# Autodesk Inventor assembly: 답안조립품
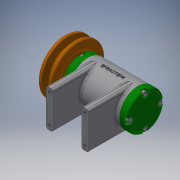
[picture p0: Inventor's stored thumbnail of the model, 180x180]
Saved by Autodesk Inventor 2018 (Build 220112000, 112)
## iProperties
Created: 2020-07
Part Number: 답안조립품
Document SubType Name: Assembly
Designer: Administrator
Author: Administrator
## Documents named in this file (15)
- C:\Users\Administrator\Desktop\700706V1038\답안조립품.iam
- C:\Users\Administrator\Desktop\700706V1038\본체 ipt.ipt
- C:\Users\Administrator\Desktop\700706V1038\V벨트풀리.ipt
- C:\Users\Administrator\Desktop\700706V1038\너트 M8.ipt
- C:\Users\Administrator\Desktop\700706V1038\뒤커버.ipt
- C:\Users\Administrator\Desktop\700706V1038\베어링 6002.ipt
- C:\Users\Administrator\Desktop\700706V1038\볼트 M4x12.ipt
- C:\Users\Administrator\Desktop\700706V1038\볼트 M6x8.ipt
- C:\Users\Administrator\Desktop\700706V1038\스프링와셔 8.ipt
- C:\Users\Administrator\Desktop\700706V1038\앞커버.ipt
- C:\Users\Administrator\Desktop\700706V1038\오일 실 15 25 7.ipt
- C:\Users\Administrator\Desktop\700706V1038\와셔 6x11.5.ipt
- C:\Users\Administrator\Desktop\700706V1038\와셔 8x17.ipt
- C:\Users\Administrator\Desktop\700706V1038\축.ipt
- C:\Users\Administrator\Desktop\700706V1038\키 3x3x12.ipt
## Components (1 placed, 1 different names)
1. V벨트풀리:1
